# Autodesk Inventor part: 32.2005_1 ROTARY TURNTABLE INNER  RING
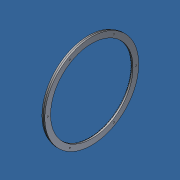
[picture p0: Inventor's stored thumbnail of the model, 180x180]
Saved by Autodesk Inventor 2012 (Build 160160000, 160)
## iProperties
Created: 2017-02
Part Number: 32.2005_1 ROTARY TURNTABLE INNER  RING
Material: Aluminum-6061
Document SubType Name: Modeling
Designer: Admin
Density: 2.71 g/cm^3
Mass: 257.704 g
Surface Area: 516.609 cm^2
Volume: 95.0939 cm^3
Author: Admin
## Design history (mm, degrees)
sketch "Sketch1"
  geometry: L1 (-5, -146)-(-11.2, -146); L2 (-11.2, -146)-(-11.2, -143); L3 (-11.2, -143)-(-5, -143); L4 (-5, -143)-(-5, -130); L5 (-5, -130)-(0, -130); L6 (0, -130)-(0, -148); L7 (-5, -146)-(-5, -148); L8 (-5, -148)-(0, -148); L9 (-13.44, 0)-(2.24, 0) reference; 1 further point
  constraints: 16 end point, 5 parallel, 2 perpendicular, 1 horizontal, 1 vertical alignment
  dimensions: "d0" = 18 distance of L5.end L6.end; "d1" = 16 distance between parallel lines of L5 L1; "d2" = 11.2 distance between parallel lines of L6 L2; "d3" = 5 distance of L4.end L5.end; "d4" = 130 distance from line of point (0, 0) L5; "d5" = 5 distance of L7.end L6.end; "d12" = 143 distance between parallel lines of L3 L9
revolve "Revolution1" sketch "Sketch1" stored, may be unused: angle "d7" = 90 deg
sketch "Sketch2"
  geometry: C1 r 130 at (0, 0) reference; C2 r 2.05 at (0, -139)
  constraints: 1 centre point, 1 vertical alignment
  dimensions: "d8" = 4.1 diameter of C2; "d9" = 139 distance of C2.centre C1.centre
extrude "Extrusion1" cut sketch "Sketch2" distance "d10" = 10; taper "d11" = 0 deg
pattern_circular "Circular Pattern1" dims angle "d14" = 360 deg
sketch "Sketch3"
  geometry: L1 (-1.5, -135.1)-(1.5, -135.1); L2 (1.5, -135.1)-(1.5, -130.9); L3 (1.5, -130.9)-(-1.5, -130.9); L4 (-1.5, -130.9)-(-1.5, -135.1); L5 (-1.5, -133)-(1.5, -133); C1 r 2.05 at (0, -139) reference; C2 r 130 at (0, 0) reference; 1 further point
  constraints: 10 end point, 3 midpoint, 2 parallel, 1 horizontal, 1 perpendicular, 1 vertical alignment
  dimensions: "d16" = 3 distance of L2.end L3.end; "d17" = 4.2 distance of L3.end L1.start; "d18" = 133 distance from line of L5 C2.centre
extrude "Extrusion2" join sketch "Sketch3" distance "d19" = 3.5; taper "d20" = -14.5 deg
body "Solid1"
pattern_circular "Circular Pattern2" dims angle "d22" = 360 deg
